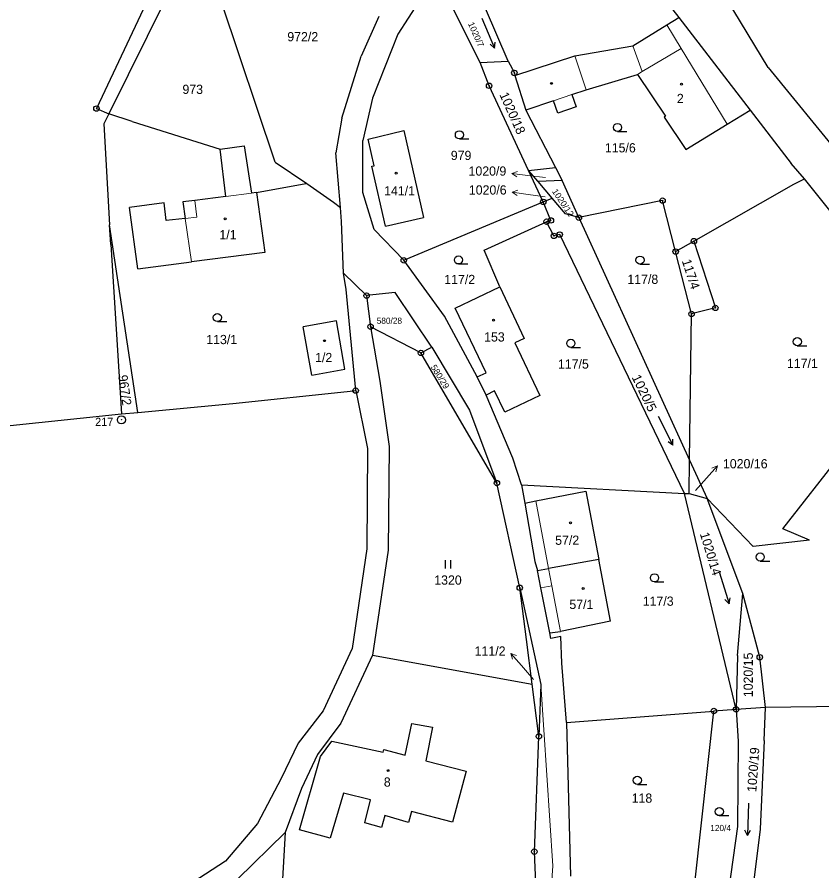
# Model space of a CAD drawing. Extents: x -601131 to -597152, y -1058536 to -1055911.
# Drawn here: x -599499.1 to -599350.8, y -1056634.8 to -1056477.3 of the extents above; entities that cross this region are included whole.
import ezdxf
from ezdxf.enums import TextEntityAlignment as Align

# ---------------------------------------------------------------- set-up
doc = ezdxf.new("R2010")
doc.units = 0
doc.header["$LTSCALE"] = 0.68
for name, color, linetype, lineweight in [('1', 7, 'Continuous', 25), ('3', 7, 'Continuous', 25), ('4', 7, 'Continuous', 13), ('5', 7, 'Continuous', 25), ('7', 7, 'Continuous', 13), ('8', 7, 'Continuous', 25)]:
    doc.layers.add(name, color=color, linetype=linetype, lineweight=lineweight)
doc.layers.add('2', color=7, linetype='Continuous')

msp = doc.modelspace()

# ---------------------------------------------------------------- linework, layer by layer
at = {"layer": '1'}
for p, q in [((-599444.98, -1056410.33), (-599484.45, -1056494.21)), ((-599394.79, -1056454.54), (-599377.16, -1056477.43)), ((-599469.97, -1056470.57), (-599482.19, -1056495.19)), ((-599360.66, -1056486.62), (-599368.22, -1056474.1)), ((-599425.14, -1056474.58), (-599428.89, -1056480.48)), ((-599413.77, -1056485.74), (-599418.88, -1056475.43)), ((-599408.6, -1056485.47), (-599412.79, -1056475.76)), ((-599432.42, -1056477.26), (-599435.66, -1056484.55)), ((-599379.39, -1056478.8), (-599377.16, -1056477.43)), ((-599377.16, -1056477.43), (-599364.02, -1056494.49)), ((-599385.65, -1056482.65), (-599379.39, -1056478.8)), ((-599428.89, -1056480.48), (-599433.6, -1056492.32)), ((-599396.29, -1056484.51), (-599385.65, -1056482.65)), ((-599439.22, -1056495.97), (-599435.66, -1056484.55)), ((-599413.77, -1056485.74), (-599408.6, -1056485.47)), ((-599408.6, -1056485.47), (-599407.45, -1056487.64)), ((-599407.37, -1056488.13), (-599396.29, -1056484.51)), ((-599412.11, -1056490.02), (-599413.77, -1056485.74)), ((-599360.66, -1056486.62), (-599347.27, -1056503.12)), ((-599407.45, -1056487.64), (-599407.37, -1056488.13)), ((-599407.37, -1056488.13), (-599405.34, -1056494.49)), ((-599394.21, -1056490.73), (-599384.78, -1056487.94)), ((-599384.78, -1056487.94), (-599379.61, -1056495.61)), ((-599404.82, -1056505.64), (-599412.11, -1056490.02)), ((-599396.84, -1056491.62), (-599394.21, -1056490.73)), ((-599396.84, -1056491.62), (-599396.07, -1056493.92)), ((-599433.6, -1056492.32), (-599435.39, -1056500.09)), ((-599400.22, -1056492.76), (-599405.34, -1056494.49)), ((-599399.45, -1056495.06), (-599400.22, -1056492.76)), ((-599484.45, -1056494.21), (-599482.19, -1056495.19)), ((-599405.34, -1056494.49), (-599399.88, -1056505.08)), ((-599396.07, -1056493.92), (-599399.45, -1056495.06)), ((-599368.24, -1056497.09), (-599364.02, -1056494.49)), ((-599364.02, -1056494.49), (-599356.45, -1056504.33)), ((-599482.19, -1056495.19), (-599483.1, -1056497.01)), ((-599477.84, -1056496.6), (-599482.19, -1056495.19)), ((-599439.22, -1056495.97), (-599440.37, -1056502.35)), ((-599379.61, -1056495.61), (-599379.87, -1056495.79)), ((-599379.87, -1056495.79), (-599375.84, -1056501.77)), ((-599483.1, -1056497.01), (-599482.04, -1056515.67)), ((-599477.84, -1056496.6), (-599461.68, -1056501.71)), ((-599375.84, -1056501.77), (-599368.24, -1056497.09)), ((-599434.38, -1056499.88), (-599427.81, -1056498.24)), ((-599427.81, -1056498.24), (-599424.16, -1056514.27)), ((-599457.22, -1056501.07), (-599455.89, -1056509.81)), ((-599435.34, -1056509.71), (-599435.39, -1056500.09)), ((-599433.26, -1056504.75), (-599434.38, -1056499.88)), ((-599439.48, -1056512.48), (-599440.37, -1056502.35)), ((-599451.49, -1056504.11), (-599445.67, -1056508)), ((-599353.98, -1056507.19), (-599356.45, -1056504.33)), ((-599433.72, -1056504.85), (-599433.26, -1056504.75)), ((-599431.19, -1056515.9), (-599433.72, -1056504.85)), ((-599404.82, -1056505.64), (-599399.88, -1056505.08)), ((-599402.12, -1056511.41), (-599404.82, -1056505.64)), ((-599403.07, -1056507.68), (-599404.82, -1056505.64)), ((-599399.88, -1056505.08), (-599398.64, -1056507.48)), ((-599398.64, -1056507.48), (-599403.07, -1056507.68)), ((-599395.56, -1056514.32), (-599398.64, -1056507.48)), ((-599344.11, -1056519.56), (-599353.98, -1056507.19)), ((-599454.93, -1056509.69), (-599445.86, -1056508.03)), ((-599445.67, -1056508), (-599445.86, -1056508.03)), ((-599445.67, -1056508), (-599440.79, -1056511.47)), ((-599400.47, -1056510.71), (-599403.07, -1056507.68)), ((-599460.6, -1056510.41), (-599466.33, -1056511.14)), ((-599454.93, -1056509.69), (-599455.89, -1056509.81)), ((-599454.93, -1056509.69), (-599453.44, -1056520.75)), ((-599433.28, -1056516.48), (-599435.34, -1056509.71)), ((-599471.95, -1056511.62), (-599478.38, -1056512.47)), ((-599471.6, -1056514.86), (-599471.95, -1056511.62)), ((-599466.33, -1056511.14), (-599468.51, -1056511.42)), ((-599468.51, -1056511.42), (-599468.08, -1056514.46)), ((-599440.79, -1056511.47), (-599439.48, -1056512.48)), ((-599427.82, -1056522.19), (-599402.12, -1056511.41)), ((-599402.12, -1056511.41), (-599400.47, -1056510.71)), ((-599400.73, -1056514.84), (-599402.12, -1056511.41)), ((-599398, -1056513.6), (-599400.47, -1056510.71)), ((-599380.14, -1056511.18), (-599395.56, -1056514.32)), ((-599377.74, -1056520.57), (-599380.14, -1056511.18)), ((-599476.84, -1056523.79), (-599478.38, -1056512.47)), ((-599439.29, -1056515.05), (-599439.48, -1056512.48)), ((-599395.56, -1056514.32), (-599398, -1056513.6)), ((-599468.08, -1056514.46), (-599471.6, -1056514.86)), ((-599438.9, -1056524.56), (-599439.29, -1056515.05)), ((-599431.19, -1056515.9), (-599424.16, -1056514.27)), ((-599413.04, -1056520.33), (-599401.5, -1056515.07)), ((-599401.5, -1056515.07), (-599400.73, -1056514.84)), ((-599400.16, -1056517.69), (-599401.5, -1056515.07)), ((-599395.56, -1056514.32), (-599375.16, -1056559.05)), ((-599481.81, -1056519.25), (-599482.04, -1056515.67)), ((-599476.8, -1056550.23), (-599482.04, -1056515.67)), ((-599427.82, -1056522.19), (-599433.28, -1056516.48)), ((-599399.1, -1056517.44), (-599400.16, -1056517.69)), ((-599376.12, -1056565.17), (-599399.1, -1056517.44)), ((-599481.81, -1056519.25), (-599479.85, -1056550.52)), ((-599377.74, -1056520.57), (-599374.37, -1056518.65)), ((-599374.37, -1056518.65), (-599370.41, -1056530.97)), ((-599453.44, -1056520.75), (-599466.96, -1056522.49)), ((-599410.15, -1056527.06), (-599413.04, -1056520.33)), ((-599374.8, -1056532.08), (-599377.74, -1056520.57)), ((-599476.84, -1056523.79), (-599466.96, -1056522.49)), ((-599420.3, -1056532.49), (-599427.82, -1056522.19)), ((-599438.45, -1056527.57), (-599438.9, -1056524.56)), ((-599438.9, -1056524.56), (-599434.67, -1056528.7)), ((-599436.68, -1056546.21), (-599438.45, -1056527.57)), ((-599418.37, -1056530.99), (-599410.15, -1056527.06)), ((-599410.15, -1056527.06), (-599405.63, -1056536.59)), ((-599429.41, -1056528.12), (-599434.67, -1056528.7)), ((-599434.67, -1056528.7), (-599433.94, -1056534.43)), ((-599422.63, -1056538.18), (-599429.41, -1056528.12)), ((-599412.67, -1056542.92), (-599418.37, -1056530.99)), ((-599370.41, -1056530.97), (-599374.8, -1056532.08)), ((-599414.32, -1056543.69), (-599420.3, -1056532.49)), ((-599375.16, -1056559.05), (-599374.8, -1056532.08)), ((-599440.22, -1056533.32), (-599446.36, -1056534.45)), ((-599438.71, -1056542.28), (-599440.22, -1056533.32)), ((-599444.76, -1056543.35), (-599446.36, -1056534.45)), ((-599424.66, -1056539.27), (-599433.94, -1056534.43)), ((-599433.94, -1056534.43), (-599432.26, -1056544.49)), ((-599405.63, -1056536.59), (-599407.38, -1056537.42)), ((-599407.38, -1056537.42), (-599402.78, -1056547.13)), ((-599424.66, -1056539.27), (-599422.63, -1056538.18)), ((-599422.63, -1056538.18), (-599415.74, -1056549.83)), ((-599410.66, -1056563.26), (-599424.66, -1056539.27)), ((-599357.98, -1056571.68), (-599333.85, -1056540.74)), ((-599444.76, -1056543.35), (-599438.71, -1056542.28)), ((-599414.32, -1056543.69), (-599412.67, -1056542.92)), ((-599412.64, -1056547.04), (-599414.32, -1056543.69)), ((-599432.26, -1056544.49), (-599430.54, -1056556.54)), ((-599438.23, -1056546.37), (-599436.68, -1056546.21)), ((-599436.68, -1056546.21), (-599434.52, -1056556.9)), ((-599411.08, -1056546.24), (-599412.64, -1056547.04)), ((-599409.21, -1056550.16), (-599411.08, -1056546.24)), ((-599407.74, -1056558.65), (-599412.64, -1056547.04)), ((-599402.78, -1056547.13), (-599409.21, -1056550.16)), ((-599415.74, -1056549.83), (-599410.66, -1056563.26)), ((-599601.78, -1056563.11), (-599479.85, -1056550.52)), ((-599479.85, -1056550.52), (-599476.8, -1056550.23)), ((-599434.52, -1056556.9), (-599434.66, -1056575.41)), ((-599430.54, -1056556.54), (-599430.67, -1056575.66)), ((-599406.14, -1056563.61), (-599407.74, -1056558.65)), ((-599375.24, -1056565.16), (-599375.16, -1056559.05)), ((-599375.16, -1056559.05), (-599371.93, -1056566.13)), ((-599406.46, -1056582.57), (-599410.66, -1056563.26)), ((-599406.14, -1056563.61), (-599376.12, -1056565.17)), ((-599406.14, -1056563.61), (-599405.51, -1056566.95)), ((-599403.51, -1056566.56), (-599394.29, -1056564.74)), ((-599394.29, -1056564.74), (-599391.89, -1056577.34)), ((-599376.12, -1056565.17), (-599375.24, -1056565.16)), ((-599366.6, -1056604.99), (-599376.12, -1056565.17)), ((-599375.24, -1056565.16), (-599371.93, -1056566.13)), ((-599405.51, -1056566.95), (-599403.51, -1056566.56)), ((-599405.51, -1056566.95), (-599403.68, -1056577.71)), ((-599363.48, -1056574.94), (-599371.93, -1056566.13)), ((-599365.36, -1056583.63), (-599371.93, -1056566.13)), ((-599353.07, -1056573.78), (-599357.98, -1056571.68)), ((-599353.07, -1056573.78), (-599363.48, -1056574.94)), ((-599434.66, -1056575.41), (-599437.36, -1056593.75)), ((-599430.67, -1056575.66), (-599433.56, -1056595)), ((-599403.68, -1056577.71), (-599403.18, -1056579.41)), ((-599391.89, -1056577.34), (-599401.14, -1056579.02)), ((-599389.71, -1056588.75), (-599391.89, -1056577.34)), ((-599403.18, -1056579.41), (-599401.14, -1056579.02)), ((-599402.58, -1056582.58), (-599403.18, -1056579.41)), ((-599406.46, -1056582.57), (-599402.59, -1056600.39)), ((-599405.19, -1056592.09), (-599406.46, -1056582.57)), ((-599400.92, -1056590.88), (-599402.58, -1056582.58)), ((-599366.34, -1056595.04), (-599365.36, -1056583.63)), ((-599362.24, -1056595.37), (-599365.36, -1056583.63)), ((-599389.71, -1056588.75), (-599398.93, -1056590.6)), ((-599400.92, -1056590.88), (-599398.93, -1056590.6)), ((-599400.71, -1056591.92), (-599400.92, -1056590.88)), ((-599404.18, -1056600.32), (-599405.19, -1056592.09)), ((-599398.88, -1056591.56), (-599400.71, -1056591.92)), ((-599398.68, -1056596.47), (-599398.88, -1056591.56)), ((-599437.36, -1056593.75), (-599442.68, -1056605.23)), ((-599433.56, -1056595), (-599439.42, -1056607.55)), ((-599433.56, -1056595), (-599404.18, -1056600.32)), ((-599366.34, -1056595.04), (-599366.6, -1056604.99)), ((-599361.21, -1056604.62), (-599362.24, -1056595.37)), ((-599397.87, -1056607.43), (-599398.68, -1056596.47)), ((-599402.94, -1056609.96), (-599404.18, -1056600.32)), ((-599402.59, -1056600.39), (-599402.94, -1056609.96)), ((-599366.6, -1056604.99), (-599370.69, -1056605.29)), ((-599361.21, -1056604.62), (-599366.6, -1056604.99)), ((-599366.6, -1056604.99), (-599366.22, -1056610.84)), ((-599361.42, -1056610.7), (-599361.21, -1056604.62)), ((-599341.43, -1056604.36), (-599361.21, -1056604.62)), ((-599442.68, -1056605.23), (-599447.29, -1056611.2)), ((-599397.87, -1056607.43), (-599370.69, -1056605.29)), ((-599374.11, -1056636.47), (-599370.69, -1056605.29)), ((-599439.42, -1056607.55), (-599443.71, -1056613.31)), ((-599427.56, -1056613.4), (-599426.36, -1056607.57)), ((-599426.36, -1056607.57), (-599422.56, -1056608.29)), ((-599397.87, -1056607.43), (-599397.08, -1056635.71)), ((-599422.56, -1056608.29), (-599423.73, -1056614.45)), ((-599447.29, -1056611.2), (-599450.41, -1056617.76)), ((-599443.19, -1056613.68), (-599441.1, -1056610.83)), ((-599441.1, -1056610.83), (-599431.65, -1056612.88)), ((-599403.77, -1056631.22), (-599402.94, -1056609.96)), ((-599366.22, -1056610.84), (-599366.33, -1056626.58)), ((-599361.42, -1056610.7), (-599362.14, -1056627.07)), ((-599431.65, -1056612.88), (-599431.51, -1056612.38)), ((-599431.51, -1056612.38), (-599427.56, -1056613.4)), ((-599447.01, -1056627.2), (-599443.19, -1056613.68)), ((-599443.71, -1056613.31), (-599446.67, -1056619.55)), ((-599423.73, -1056614.45), (-599416.34, -1056616.38)), ((-599416.34, -1056616.38), (-599418.85, -1056625.78)), ((-599450.41, -1056617.76), (-599454.75, -1056626.04)), ((-599446.67, -1056619.55), (-599449.68, -1056627.67)), ((-599438.95, -1056620.45), (-599441.4, -1056628.75)), ((-599433.93, -1056621.65), (-599438.95, -1056620.45)), ((-599435, -1056625.92), (-599433.93, -1056621.65)), ((-599426.4, -1056623.82), (-599426.93, -1056625.85)), ((-599418.85, -1056625.78), (-599426.4, -1056623.82)), ((-599431.34, -1056624.57), (-599431.94, -1056626.76)), ((-599426.93, -1056625.85), (-599431.34, -1056624.57)), ((-599454.75, -1056626.04), (-599460.68, -1056633)), ((-599431.94, -1056626.76), (-599435, -1056625.92)), ((-599366.33, -1056626.58), (-599368.17, -1056639.78)), ((-599362.14, -1056627.07), (-599364, -1056641.99)), ((-599449.68, -1056627.67), (-599458.47, -1056636.3)), ((-599449.68, -1056627.67), (-599451.05, -1056652.02)), ((-599441.4, -1056628.75), (-599447.01, -1056627.2)), ((-599403.11, -1056645.83), (-599403.77, -1056631.22)), ((-599460.68, -1056633), (-599472.84, -1056640.82))]:
    msp.add_line(p, q, dxfattribs=at)
for points in [[(-599451.49, -1056504.11), (-599461.42, -1056474.62), (-599453.95, -1056456.84)], [(-599460.6, -1056510.41), (-599461.68, -1056501.71), (-599457.22, -1056501.07)], [(-599374.37, -1056518.65), (-599355.96, -1056508.16), (-599353.98, -1056507.19)], [(-599476.8, -1056550.23), (-599459.31, -1056548.57), (-599438.23, -1056546.37)]]:
    msp.add_lwpolyline(points, dxfattribs=at)
at = {"layer": '3'}
for p, q in [((-599411.079, -1056483.071), (-599411.922, -1056482.367)), ((-599388.453, -1056498.44), (-599386.703, -1056498.44)), ((-599417.573, -1056499.8), (-599415.823, -1056499.8)), ((-599417.753, -1056522.87), (-599416.003, -1056522.87)), ((-599384.313, -1056522.9), (-599382.563, -1056522.9)), ((-599462.163, -1056533.5), (-599460.413, -1056533.5)), ((-599397.043, -1056538.26), (-599395.293, -1056538.26)), ((-599355.323, -1056537.95), (-599353.573, -1056537.95)), ((-599378.238, -1056556.282), (-599379.128, -1056555.639)), ((-599420.151, -1056579), (-599420.151, -1056577.5)), ((-599419.15, -1056579), (-599419.15, -1056577.5)), ((-599362.153, -1056577.65), (-599360.403, -1056577.65)), ((-599381.633, -1056581.49), (-599379.883, -1056581.49)), ((-599367.896, -1056585.518), (-599368.661, -1056584.73)), ((-599384.783, -1056618.81), (-599383.033, -1056618.81)), ((-599369.693, -1056624.58), (-599367.943, -1056624.58)), ((-599364.494, -1056628.245), (-599364.961, -1056627.251))]:
    msp.add_line(p, q, dxfattribs=at)
for points in [[(-599413.423, -1056477.548), (-599411.079, -1056483.071), (-599410.999, -1056481.975)], [(-599380.962, -1056550.936), (-599378.238, -1056556.282), (-599378.235, -1056555.184)], [(-599369.65, -1056579.78), (-599367.896, -1056585.518), (-599367.702, -1056584.437)], [(-599364.284, -1056622.249), (-599364.494, -1056628.245), (-599363.959, -1056627.286)]]:
    msp.add_lwpolyline(points, dxfattribs=at)
for centre in [(-599388.4529, -1056497.6898), (-599417.5729, -1056499.0498), (-599417.7529, -1056522.1198), (-599384.3129, -1056522.1498), (-599462.1629, -1056532.7498), (-599397.0429, -1056537.5098), (-599355.3229, -1056537.1998), (-599362.1529, -1056576.8998), (-599381.6329, -1056580.7398), (-599384.7829, -1056618.0598), (-599369.6929, -1056623.8298)]:
    msp.add_circle(centre, 0.75, dxfattribs=at)
at = {"layer": '4'}
for p, q in [((-599376.74, -1056483.15), (-599379.39, -1056478.8)), ((-599385.65, -1056482.65), (-599383.88, -1056487.4)), ((-599383.88, -1056487.4), (-599376.74, -1056483.15)), ((-599368.24, -1056497.09), (-599376.74, -1056483.15)), ((-599394.21, -1056490.73), (-599396.29, -1056484.51)), ((-599383.88, -1056487.4), (-599384.78, -1056487.94)), ((-599400.22, -1056492.76), (-599396.84, -1056491.62)), ((-599455.89, -1056509.81), (-599460.6, -1056510.41)), ((-599466.33, -1056511.14), (-599465.94, -1056514.22)), ((-599465.94, -1056514.22), (-599468.08, -1056514.46)), ((-599468.08, -1056514.46), (-599466.96, -1056522.49)), ((-599401.14, -1056579.02), (-599403.51, -1056566.56)), ((-599400.53, -1056582.18), (-599401.14, -1056579.02)), ((-599402.58, -1056582.58), (-599400.53, -1056582.18)), ((-599400.53, -1056582.18), (-599398.93, -1056590.6)), ((-599402.59, -1056600.39), (-599400.35, -1056633.83)), ((-599401.33, -1056648.71), (-599400.35, -1056633.83))]:
    msp.add_line(p, q, dxfattribs=at)
at = {"layer": '5'}
for centre in [(-599400.6068, -1056489.5692), (-599376.6468, -1056489.7192), (-599429.2268, -1056506.1292), (-599460.7468, -1056514.5292), (-599411.2668, -1056533.2192), (-599442.4268, -1056537.0092), (-599397.1268, -1056570.6092), (-599394.7668, -1056582.6992), (-599430.7268, -1056616.2792)]:
    msp.add_circle(centre, 0.175, dxfattribs=at)
at = {"layer": '7'}
for p, q in [((-599407.939, -1056506.164), (-599407.006, -1056506.783)), ((-599407.882, -1056509.632), (-599406.96, -1056510.268)), ((-599370.022, -1056560.11), (-599371.064, -1056560.519)), ((-599408.089, -1056594.655), (-599407.81, -1056595.739))]:
    msp.add_line(p, q, dxfattribs=at)
for points in [[(-599401.74, -1056506.93), (-599404.96, -1056506.53), (-599407.939, -1056506.164), (-599406.884, -1056505.789)], [(-599401.8, -1056510.47), (-599404.91, -1056510.05), (-599407.882, -1056509.632), (-599406.82, -1056509.276)], [(-599374.09, -1056564.61), (-599372.03, -1056562.34), (-599370.022, -1056560.11), (-599370.32, -1056561.189)], [(-599403.92, -1056599.47), (-599406.12, -1056596.92), (-599408.089, -1056594.655), (-599407.054, -1056595.082)]]:
    msp.add_lwpolyline(points, dxfattribs=at)
at = {"layer": '8'}
for centre, radius in [((-599407.45, -1056487.6399), 0.5), ((-599407.45, -1056487.6399), 0.0303), ((-599412.11, -1056490.0199), 0.5), ((-599412.11, -1056490.0199), 0.0303), ((-599484.45, -1056494.2099), 0.5), ((-599484.45, -1056494.2099), 0.0303), ((-599402.12, -1056511.4099), 0.5), ((-599402.12, -1056511.4099), 0.0303), ((-599380.14, -1056511.1799), 0.5), ((-599380.14, -1056511.1799), 0.0303), ((-599401.5, -1056515.0699), 0.5), ((-599401.5, -1056515.0699), 0.0303), ((-599400.73, -1056514.8399), 0.5), ((-599400.73, -1056514.8399), 0.0303), ((-599395.56, -1056514.3199), 0.5), ((-599395.56, -1056514.3199), 0.0303), ((-599399.1, -1056517.4399), 0.5), ((-599400.16, -1056517.6899), 0.5), ((-599400.16, -1056517.6899), 0.0303), ((-599399.1, -1056517.4399), 0.0303), ((-599374.37, -1056518.6499), 0.5), ((-599377.74, -1056520.5699), 0.5), ((-599374.37, -1056518.6499), 0.0303), ((-599377.74, -1056520.5699), 0.0303), ((-599427.82, -1056522.1899), 0.5), ((-599427.82, -1056522.1899), 0.0303), ((-599434.67, -1056528.6999), 0.5), ((-599434.67, -1056528.6999), 0.0303), ((-599370.41, -1056530.9699), 0.5), ((-599370.41, -1056530.9699), 0.0303), ((-599374.8, -1056532.0799), 0.5), ((-599374.8, -1056532.0799), 0.0303), ((-599433.94, -1056534.4299), 0.5), ((-599433.94, -1056534.4299), 0.0303), ((-599424.66, -1056539.2699), 0.5), ((-599424.66, -1056539.2699), 0.0303), ((-599436.68, -1056546.2099), 0.5), ((-599436.68, -1056546.2099), 0.0303), ((-599479.84, -1056551.5998), 0.75), ((-599479.84, -1056551.5998), 0.03), ((-599410.66, -1056563.2599), 0.5), ((-599410.66, -1056563.2599), 0.0303), ((-599406.46, -1056582.5699), 0.5), ((-599406.46, -1056582.5699), 0.0303), ((-599362.24, -1056595.3699), 0.5), ((-599362.24, -1056595.3699), 0.0303), ((-599370.69, -1056605.2899), 0.5), ((-599366.6, -1056604.9899), 0.5), ((-599366.6, -1056604.9899), 0.0303), ((-599370.69, -1056605.2899), 0.0303), ((-599402.94, -1056609.9599), 0.5), ((-599402.94, -1056609.9599), 0.0303), ((-599403.77, -1056631.2199), 0.5), ((-599403.77, -1056631.2199), 0.0303)]:
    msp.add_circle(centre, radius, dxfattribs=at)

# ---------------------------------------------------------------- texts
at = {"layer": '2', "width": 1.05}
for s, height, rotation, p in [('1020/7', 1.14, 294, (-599416.03, -1056478.555)), ('1020/12', 1.14, 304, (-599400.576, -1056509.479)), ('580/29', 1.14, 302, (-599422.911, -1056541.881)), ('1020/5', 1.7, 296, (-599385.871, -1056543.736))]:
    msp.add_text(s, height=height, rotation=rotation, dxfattribs=at).set_placement(p)
at = {"layer": '2'}
for s, height, p in [('972/2', 1.7, (-599449.28, -1056481.814)), ('973', 1.7, (-599468.6, -1056491.515)), ('2', 1.7, (-599377.51, -1056493.205)), ('115/6', 1.7, (-599390.77, -1056502.295)), ('979', 1.7, (-599419.16, -1056503.705)), ('141/1', 1.7, (-599431.45, -1056510.225)), ('1/1', 1.7, (-599461.8, -1056518.324)), ('117/2', 1.7, (-599420.37, -1056526.574)), ('117/8', 1.7, (-599386.63, -1056526.535)), ('580/28', 1.14, (-599432.81, -1056533.895)), ('153', 1.7, (-599413.02, -1056537.165)), ('113/1', 1.7, (-599464.21, -1056537.645)), ('1/2', 1.7, (-599444.16, -1056540.965)), ('117/5', 1.7, (-599399.42, -1056542.155)), ('117/1', 1.7, (-599357.24, -1056542.045)), ('1020/16', 1.7, (-599369.02, -1056560.545)), ('57/2', 1.7, (-599399.93, -1056574.645)), ('117/3', 1.7, (-599383.8, -1056585.885)), ('57/1', 1.7, (-599397.32, -1056586.485)), ('118', 1.7, (-599385.84, -1056622.195)), ('120/4', 1.14, (-599371.36, -1056627.424))]:
    msp.add_text(s, height=height, dxfattribs=at).set_placement(p)
for s, rotation, p in [('1020/18', 294, (-599410.228, -1056491.642)), ('117/4', 288, (-599376.614, -1056522.291)), ('967/2', 278, (-599480.44, -1056543.429)), ('1020/14', 287, (-599373.296, -1056572.614)), ('1020/15', 90, (-599363.515, -1056602.73)), ('1020/19', 86, (-599362.876, -1056620.259))]:
    msp.add_text(s, height=1.7, rotation=rotation, dxfattribs=at).set_placement(p)
for s, p in [('1020/9', (-599408.939, -1056506.584)), ('1020/6', (-599408.879, -1056510.064)), ('111/2', (-599409.08, -1056595.074))]:
    msp.add_text(s, height=1.7, dxfattribs=at).set_placement(p, align=Align.RIGHT)
for s, p in [('1320', (-599419.68, -1056581.992)), ('8', (-599430.87, -1056619.232))]:
    msp.add_text(s, height=1.7, dxfattribs=at).set_placement(p, align=Align.CENTER)
at = {"layer": '8'}
msp.add_text('217', height=1.5, dxfattribs=at).set_placement((-599481.339, -1056552.717), align=Align.RIGHT)

doc.saveas('drawing.dxf')
